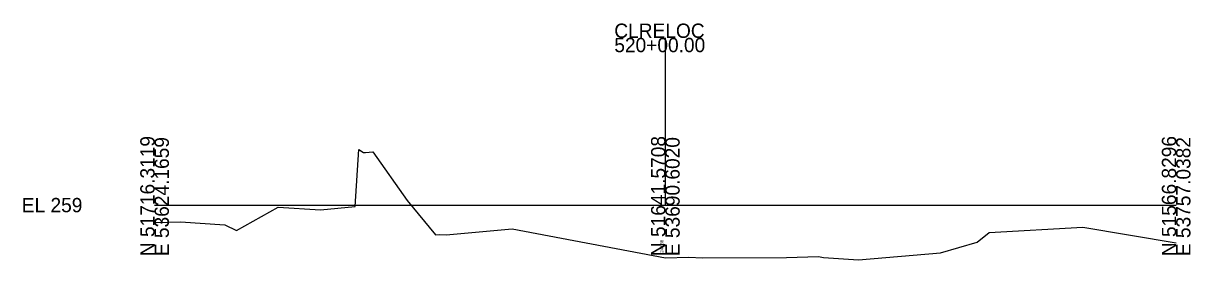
# Model space of a CAD drawing. Extents: x 6376 to 6605, y 90969 to 95005.
# Drawn here: x 6376.3 to 6604.8, y 92967.8 to 93014.1 of the extents above; entities that cross this region are included whole.
import ezdxf

# ---------------------------------------------------------------- set-up
doc = ezdxf.new("R2010")
doc.units = 0
for name, color, linetype in [('Level 10', 7, 'Continuous'), ('Level 60', 7, 'Continuous'), ('Level 63', 7, 'Continuous')]:
    doc.layers.add(name, color=color, linetype=linetype)

msp = doc.modelspace()

# ---------------------------------------------------------------- linework, layer by layer
at = {"layer": 'Level 60'}
for p, q in [((6441.24, 92978.23), (6441.96, 92989.44)), ((6441.96, 92989.44), (6442.91, 92988.82)), ((6442.91, 92988.82), (6443.32, 92988.82)), ((6443.32, 92988.82), (6444.7, 92988.98)), ((6444.7, 92988.98), (6451.43, 92979.44)), ((6451.43, 92979.44), (6457, 92972.7)), ((6418.06, 92973.53), (6426.17, 92978.15)), ((6426.17, 92978.15), (6434.45, 92977.62)), ((6434.45, 92977.62), (6441.24, 92978.23)), ((6402, 92975.11), (6407.08, 92975.25)), ((6407.08, 92975.25), (6415.78, 92974.64)), ((6415.78, 92974.64), (6418.06, 92973.53)), ((6457, 92972.7), (6457.77, 92972.75)), ((6457.77, 92972.75), (6459.07, 92972.72)), ((6459.07, 92972.72), (6472, 92973.89)), ((6472, 92973.89), (6502, 92968.2)), ((6563.03, 92971.27), (6565.4, 92973.13)), ((6565.4, 92973.13), (6583.72, 92974.18)), ((6583.72, 92974.18), (6602, 92971.13)), ((6555.84, 92969.21), (6563.03, 92971.27)), ((6502, 92968.2), (6506.56, 92968.34)), ((6506.56, 92968.34), (6509.35, 92968.21)), ((6509.35, 92968.21), (6525.71, 92968.29)), ((6525.71, 92968.29), (6532, 92968.47)), ((6532, 92968.47), (6532.95, 92968.26)), ((6532.95, 92968.26), (6539.8, 92967.84)), ((6539.8, 92967.84), (6555.84, 92969.21))]:
    msp.add_line(p, q, dxfattribs=at)
at = {"layer": 'Level 63'}
for p, q in [((6502, 92978.53), (6502, 93011.27)), ((6402, 92978.53), (6502, 92978.53)), ((6502, 92978.53), (6602, 92978.53))]:
    msp.add_line(p, q, dxfattribs=at)

# ---------------------------------------------------------------- texts
at = {"layer": 'Level 10'}
msp.add_text('248.68', height=0.6, rotation=90, dxfattribs=at).set_placement((6501.6, 92969.2))
at = {"layer": 'Level 63'}
for s, p in [('CLRELOC', (6492, 93011.27)), ('520+00.00', (6492, 93008.47)), ('EL 259', (6376, 92977.13))]:
    msp.add_text(s, height=2.8, dxfattribs=at).set_placement(p)
for s, p in [('N 51716.3119', (6402, 92968.53)), ('E 53624.1659', (6404.8, 92968.53)), ('N 51641.5708', (6502, 92968.53)), ('E 53690.6020', (6504.8, 92968.53)), ('N 51566.8296', (6602, 92968.53)), ('E 53757.0382', (6604.8, 92968.53))]:
    msp.add_text(s, height=2.8, rotation=90, dxfattribs=at).set_placement(p)

doc.saveas('drawing.dxf')
